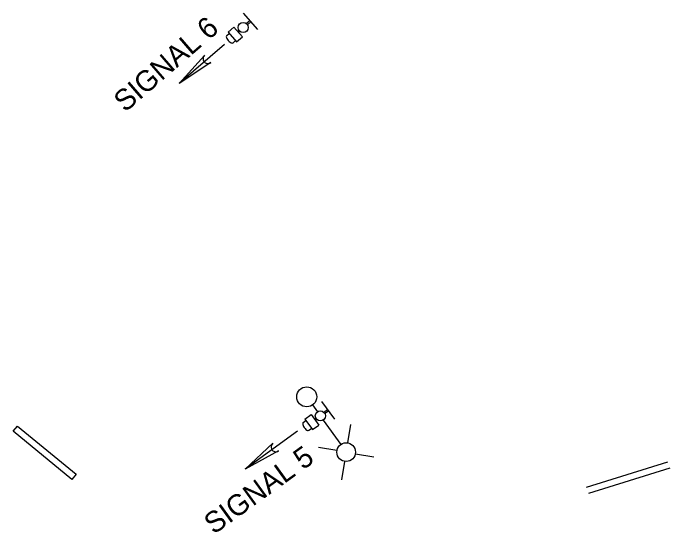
# Model space of a CAD drawing. Extents: x 2047712 to 2051245, y 280285 to 283042.
# Drawn here: x 2047845 to 2047943.3, y 281559.2 to 281637.1 of the extents above; entities that cross this region are included whole.
import ezdxf

# ---------------------------------------------------------------- set-up
doc = ezdxf.new("R2010")
doc.units = 0
doc.layers.add('RW_X_CL_100_Stations', color=7, linetype='Continuous')
doc.layers.add('SC_Scratch1', color=7, linetype='Continuous')

msp = doc.modelspace()

# ---------------------------------------------------------------- linework, layer by layer
at = {"layer": 'RW_X_CL_100_Stations'}
for p, q in [((2047879.448, 281637.052), (2047881.572, 281634.605)), ((2047880.431, 281635.919), (2047879.932, 281635.485)), ((2047880.588, 281635.738), (2047880.089, 281635.304)), ((2047877.18, 281634.221), (2047878.047, 281634.972)), ((2047878.047, 281634.972), (2047879.318, 281633.506)), ((2047876.974, 281633.711), (2047877.34, 281634.029)), ((2047877.18, 281634.221), (2047878.453, 281632.755)), ((2047878.804, 281634.504), (2047878.604, 281634.33)), ((2047878.961, 281634.323), (2047878.761, 281634.149)), ((2047877.919, 281632.623), (2047878.284, 281632.94)), ((2047878.453, 281632.755), (2047879.318, 281633.506)), ((2047876.642, 281632.385), (2047869.876, 281626.53)), ((2047869.876, 281626.53), (2047873.67, 281630.742)), ((2047874.59, 281629.68), (2047869.876, 281626.53)), ((2047891.178, 281578.956), (2047893.079, 281576.333)), ((2047889.814, 281578.454), (2047890.546, 281577.427)), ((2047892.058, 281577.742), (2047891.523, 281577.353)), ((2047888.671, 281576.335), (2047889.6, 281577.007)), ((2047889.6, 281577.007), (2047890.739, 281575.436)), ((2047892.199, 281577.547), (2047891.664, 281577.159)), ((2047888.421, 281575.845), (2047888.813, 281576.129)), ((2047888.671, 281576.335), (2047889.811, 281574.763)), ((2047890.313, 281576.474), (2047890.099, 281576.319)), ((2047890.454, 281576.28), (2047890.24, 281576.124)), ((2047891.43, 281576.198), (2047894.038, 281572.539)), ((2047889.267, 281574.678), (2047889.659, 281574.961)), ((2047889.811, 281574.763), (2047890.739, 281575.436)), ((2047895.081, 281572.779), (2047895.545, 281575.544)), ((2047887.582, 281574.527), (2047879.754, 281568.87)), ((2047879.754, 281568.87), (2047883.901, 281572.734)), ((2047893.471, 281571.631), (2047890.706, 281572.095)), ((2047884.724, 281571.596), (2047879.754, 281568.87)), ((2047896.229, 281571.169), (2047898.995, 281570.706)), ((2047894.619, 281570.021), (2047894.156, 281567.256))]:
    msp.add_line(p, q, dxfattribs=at)
for centre, radius in [((2047879.447, 281634.904), 0.757), ((2047888.944, 281579.674), 1.498), ((2047890.988, 281576.816), 0.757), ((2047894.85, 281571.4), 1.398)]:
    msp.add_circle(centre, radius, dxfattribs=at)
for centre, radius, start, end in [((2047874.13, 281630.211), 0.703, 130.87043, 310.87043), ((2047884.313, 281572.165), 0.702, 125.85487, 305.85487)]:
    msp.add_arc(centre, radius, start, end, dxfattribs=at)
for centre, major_axis in [((2047877.447, 281633.167), (-0.472, 0.544)), ((2047888.844, 281575.261), (-0.423, 0.584))]:
    msp.add_ellipse(centre, major_axis=major_axis, ratio=0.45371, start_param=0, end_param=3.141593, dxfattribs=at)
at = {"layer": 'SC_Scratch1'}
for p, q in [((2047930.79, 281566.186), (2047942.974, 281569.934)), ((2047943.28, 281568.982), (2047931.084, 281565.231))]:
    msp.add_line(p, q, dxfattribs=at)
msp.add_lwpolyline([(2047845.022, 281574.526), (2047845.671, 281575.287), (2047854.452, 281568.106), (2047853.818, 281567.332)], close=True, dxfattribs=at)

# ---------------------------------------------------------------- texts
at = {"layer": 'RW_X_CL_100_Stations'}
for s, rotation, p in [('SIGNAL 6', 40.87043, (2047861.772, 281622.127)), ('SIGNAL 5', 35.85487, (2047875.039, 281559.008))]:
    msp.add_text(s, height=3.125, rotation=rotation, dxfattribs=at).set_placement(p)

doc.saveas('drawing.dxf')
